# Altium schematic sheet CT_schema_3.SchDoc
size 298 x 230 mm
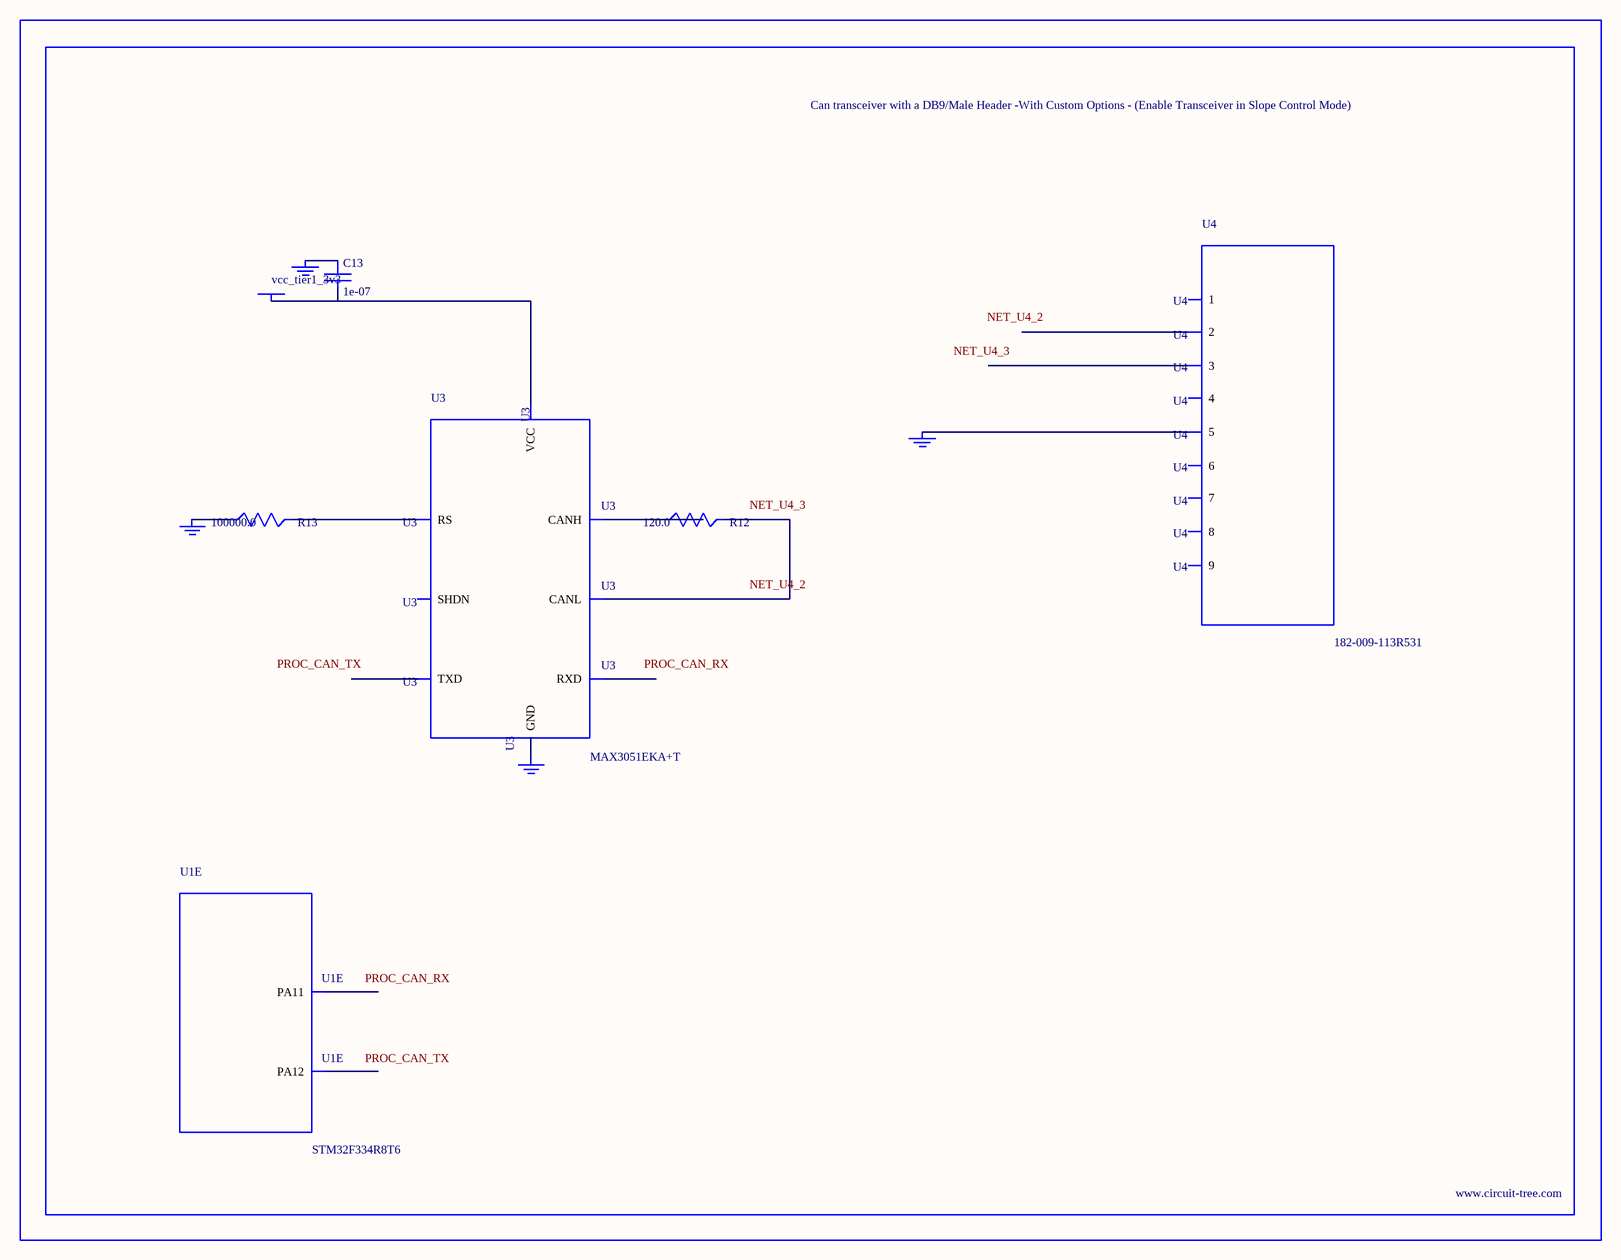
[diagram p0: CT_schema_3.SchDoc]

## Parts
BORDER2  (no value)
C13  1e-07  [C0402]
GND_INSTANCE_2_0  (no value)
GND_INSTANCE_2_1  (no value)
GND_INSTANCE_2_2  (no value)
GND_INSTANCE_2_3  (no value)
POWER_INSTANCE_2_0  vcc_tier1_3v3
R12  120.0  [R0603]
R13  100000.0  [R0603]
U1  STM32F334R8T6  [LQFP64]  (part E of 7)
U3  MAX3051EKA+T  [SOT-23-8]
U4  182-009-113R531  [182-009-MALE]

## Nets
NetC13_1: C13.1 GND_INSTANCE_2_0.0(GND)
NetC13_2: C13.2 POWER_INSTANCE_2_0.0(PWR) U3.3(VCC)
NetGND_INSTANCE_2_1_0: GND_INSTANCE_2_1.0(GND) R13.1
NetGND_INSTANCE_2_2_0: GND_INSTANCE_2_2.0(GND) U3.2(GND)
NetGND_INSTANCE_2_3_0: GND_INSTANCE_2_3.0(GND) U4.5
NetR12_1: R12.1 U3.7(CANH)
NetR12_2: R12.2 U3.6(CANL)
NetR13_2: R13.2 U3.8(RS)

Not connected (* = marked no-connect by the designer): U1 44(PA11) 45(PA12); U3 1(TXD) 4(RXD) 5(SHDN); U4 1 2 3 4 6 7 8 9

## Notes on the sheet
- Labels drawn without touching a wire or pin: NET_U4_2, NET_U4_3, PROC_CAN_RX, PROC_CAN_TX

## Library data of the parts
BORDER2 = BORDER_PAGE2
C13 = C0402C104K3RACTU
GND_INSTANCE_2_0-GND_INSTANCE_2_3 = GND
POWER_INSTANCE_2_0 = PWR
R12 = RC0603JR-07120RL
R13 = RC0603JR-07100KL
